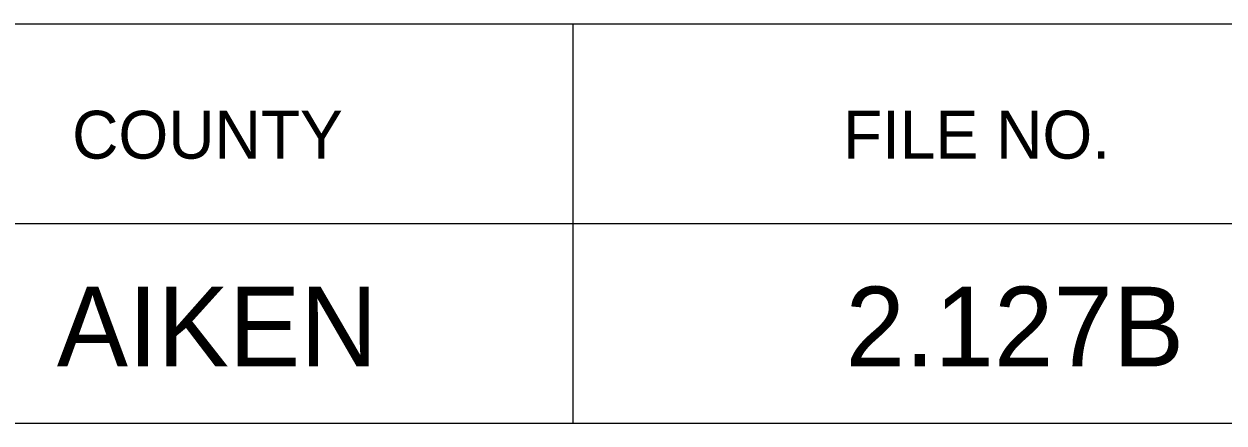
# Model space of a CAD drawing. Extents: x 1000 to 1162, y 999 to 8520.
# Drawn here: x 1140.57 to 1148.08, y 6160.05 to 6162.55 of the extents above; entities that cross this region are included whole.
import ezdxf

# ---------------------------------------------------------------- set-up
doc = ezdxf.new("R2010")
doc.units = 0
doc.layers.add('Level 20', color=7, linetype='Continuous')
doc.layers.add('Level 3', color=7, linetype='Continuous')

msp = doc.modelspace()

# ---------------------------------------------------------------- linework, layer by layer
at = {"layer": 'Level 3'}
for p, q in [((1133.055, 6162.5458), (1161.555, 6162.5458)), ((1133.055, 6162.5458), (1161.555, 6162.5458)), ((1133.055, 6162.5458), (1161.555, 6162.5458)), ((1133.055, 6162.5458), (1161.555, 6162.5458)), ((1133.055, 6162.5458), (1161.555, 6162.5458)), ((1133.055, 6162.5458), (1161.555, 6162.5458)), ((1133.055, 6162.5458), (1161.555, 6162.5458)), ((1133.055, 6162.5458), (1161.555, 6162.5458)), ((1133.055, 6162.5458), (1161.555, 6162.5458)), ((1133.055, 6162.5458), (1161.555, 6162.5458)), ((1133.055, 6162.5458), (1161.555, 6162.5458)), ((1133.055, 6162.5458), (1161.555, 6162.5458)), ((1133.055, 6162.5458), (1161.555, 6162.5458)), ((1133.055, 6162.5458), (1161.555, 6162.5458)), ((1133.055, 6162.5458), (1161.555, 6162.5458)), ((1133.055, 6162.5458), (1161.555, 6162.5458)), ((1133.055, 6162.5458), (1161.555, 6162.5458)), ((1133.055, 6162.5458), (1161.555, 6162.5458)), ((1133.055, 6162.5458), (1161.555, 6162.5458)), ((1133.055, 6162.5458), (1161.555, 6162.5458)), ((1133.055, 6162.5458), (1161.555, 6162.5458)), ((1133.055, 6162.5458), (1161.555, 6162.5458)), ((1133.055, 6162.5458), (1161.555, 6162.5458)), ((1133.055, 6162.5458), (1161.555, 6162.5458)), ((1133.055, 6162.5458), (1161.555, 6162.5458)), ((1133.055, 6162.5458), (1161.555, 6162.5458)), ((1133.055, 6162.5458), (1161.555, 6162.5458)), ((1133.055, 6162.5458), (1161.555, 6162.5458)), ((1133.055, 6162.5458), (1161.555, 6162.5458)), ((1133.055, 6162.5458), (1161.555, 6162.5458)), ((1133.055, 6162.5458), (1161.555, 6162.5458)), ((1133.055, 6162.5458), (1161.555, 6162.5458)), ((1133.055, 6162.5458), (1161.555, 6162.5458)), ((1133.055, 6162.5458), (1161.555, 6162.5458)), ((1133.055, 6162.5458), (1161.555, 6162.5458)), ((1133.055, 6162.5458), (1161.555, 6162.5458)), ((1133.055, 6162.5458), (1161.555, 6162.5458)), ((1133.055, 6162.5458), (1161.555, 6162.5458)), ((1133.055, 6162.5458), (1161.555, 6162.5458)), ((1133.055, 6162.5458), (1161.555, 6162.5458)), ((1133.055, 6162.5458), (1161.555, 6162.5458)), ((1133.055, 6162.5458), (1161.555, 6162.5458)), ((1133.055, 6162.5458), (1161.555, 6162.5458)), ((1143.9997, 6162.5458), (1143.9997, 6160.0458)), ((1143.9997, 6162.5458), (1143.9997, 6160.0458)), ((1143.9997, 6162.5458), (1143.9997, 6160.0458)), ((1143.9997, 6162.5458), (1143.9997, 6160.0458)), ((1143.9997, 6162.5458), (1143.9997, 6160.0458)), ((1143.9997, 6162.5458), (1143.9997, 6160.0458)), ((1143.9997, 6162.5458), (1143.9997, 6160.0458)), ((1143.9997, 6162.5458), (1143.9997, 6160.0458)), ((1143.9997, 6162.5458), (1143.9997, 6160.0458)), ((1143.9997, 6162.5458), (1143.9997, 6160.0458)), ((1143.9997, 6162.5458), (1143.9997, 6160.0458)), ((1143.9997, 6162.5458), (1143.9997, 6160.0458)), ((1143.9997, 6162.5458), (1143.9997, 6160.0458)), ((1143.9997, 6162.5458), (1143.9997, 6160.0458)), ((1143.9997, 6162.5458), (1143.9997, 6160.0458)), ((1143.9997, 6162.5458), (1143.9997, 6160.0458)), ((1143.9997, 6162.5458), (1143.9997, 6160.0458)), ((1143.9997, 6162.5458), (1143.9997, 6160.0458)), ((1143.9997, 6162.5458), (1143.9997, 6160.0458)), ((1143.9997, 6162.5458), (1143.9997, 6160.0458)), ((1143.9997, 6162.5458), (1143.9997, 6160.0458)), ((1143.9997, 6162.5458), (1143.9997, 6160.0458)), ((1143.9997, 6162.5458), (1143.9997, 6160.0458)), ((1143.9997, 6162.5458), (1143.9997, 6160.0458)), ((1143.9997, 6162.5458), (1143.9997, 6160.0458)), ((1143.9997, 6162.5458), (1143.9997, 6160.0458)), ((1143.9997, 6162.5458), (1143.9997, 6160.0458)), ((1143.9997, 6162.5458), (1143.9997, 6160.0458)), ((1143.9997, 6162.5458), (1143.9997, 6160.0458)), ((1143.9997, 6162.5458), (1143.9997, 6160.0458)), ((1143.9997, 6162.5458), (1143.9997, 6160.0458)), ((1143.9997, 6162.5458), (1143.9997, 6160.0458)), ((1143.9997, 6162.5458), (1143.9997, 6160.0458)), ((1143.9997, 6162.5458), (1143.9997, 6160.0458)), ((1143.9997, 6162.5458), (1143.9997, 6160.0458)), ((1143.9997, 6162.5458), (1143.9997, 6160.0458)), ((1143.9997, 6162.5458), (1143.9997, 6160.0458)), ((1143.9997, 6162.5458), (1143.9997, 6160.0458)), ((1143.9997, 6162.5458), (1143.9997, 6160.0458)), ((1143.9997, 6162.5458), (1143.9997, 6160.0458)), ((1143.9997, 6162.5458), (1143.9997, 6160.0458)), ((1143.9997, 6162.5458), (1143.9997, 6160.0458)), ((1143.9997, 6162.5458), (1143.9997, 6160.0458)), ((1133.055, 6161.2958), (1161.555, 6161.2958)), ((1133.055, 6161.2958), (1161.555, 6161.2958)), ((1133.055, 6161.2958), (1161.555, 6161.2958)), ((1133.055, 6161.2958), (1161.555, 6161.2958)), ((1133.055, 6161.2958), (1161.555, 6161.2958)), ((1133.055, 6161.2958), (1161.555, 6161.2958)), ((1133.055, 6161.2958), (1161.555, 6161.2958)), ((1133.055, 6161.2958), (1161.555, 6161.2958)), ((1133.055, 6161.2958), (1161.555, 6161.2958)), ((1133.055, 6161.2958), (1161.555, 6161.2958)), ((1133.055, 6161.2958), (1161.555, 6161.2958)), ((1133.055, 6161.2958), (1161.555, 6161.2958)), ((1133.055, 6161.2958), (1161.555, 6161.2958)), ((1133.055, 6161.2958), (1161.555, 6161.2958)), ((1133.055, 6161.2958), (1161.555, 6161.2958)), ((1133.055, 6161.2958), (1161.555, 6161.2958)), ((1133.055, 6161.2958), (1161.555, 6161.2958)), ((1133.055, 6161.2958), (1161.555, 6161.2958)), ((1133.055, 6161.2958), (1161.555, 6161.2958)), ((1133.055, 6161.2958), (1161.555, 6161.2958)), ((1133.055, 6161.2958), (1161.555, 6161.2958)), ((1133.055, 6161.2958), (1161.555, 6161.2958)), ((1133.055, 6161.2958), (1161.555, 6161.2958)), ((1133.055, 6161.2958), (1161.555, 6161.2958)), ((1133.055, 6161.2958), (1161.555, 6161.2958)), ((1133.055, 6161.2958), (1161.555, 6161.2958)), ((1133.055, 6161.2958), (1161.555, 6161.2958)), ((1133.055, 6161.2958), (1161.555, 6161.2958)), ((1133.055, 6161.2958), (1161.555, 6161.2958)), ((1133.055, 6161.2958), (1161.555, 6161.2958)), ((1133.055, 6161.2958), (1161.555, 6161.2958)), ((1133.055, 6161.2958), (1161.555, 6161.2958)), ((1133.055, 6161.2958), (1161.555, 6161.2958)), ((1133.055, 6161.2958), (1161.555, 6161.2958)), ((1133.055, 6161.2958), (1161.555, 6161.2958)), ((1133.055, 6161.2958), (1161.555, 6161.2958)), ((1133.055, 6161.2958), (1161.555, 6161.2958)), ((1133.055, 6161.2958), (1161.555, 6161.2958)), ((1133.055, 6161.2958), (1161.555, 6161.2958)), ((1133.055, 6161.2958), (1161.555, 6161.2958)), ((1133.055, 6161.2958), (1161.555, 6161.2958)), ((1133.055, 6161.2958), (1161.555, 6161.2958)), ((1133.055, 6161.2958), (1161.555, 6161.2958)), ((1133.055, 6160.0458), (1161.555, 6160.0458)), ((1133.055, 6160.0458), (1161.555, 6160.0458)), ((1133.055, 6160.0458), (1161.555, 6160.0458)), ((1133.055, 6160.0458), (1161.555, 6160.0458)), ((1133.055, 6160.0458), (1161.555, 6160.0458)), ((1133.055, 6160.0458), (1161.555, 6160.0458)), ((1133.055, 6160.0458), (1161.555, 6160.0458)), ((1133.055, 6160.0458), (1161.555, 6160.0458)), ((1133.055, 6160.0458), (1161.555, 6160.0458)), ((1133.055, 6160.0458), (1161.555, 6160.0458)), ((1133.055, 6160.0458), (1161.555, 6160.0458)), ((1133.055, 6160.0458), (1161.555, 6160.0458)), ((1133.055, 6160.0458), (1161.555, 6160.0458)), ((1133.055, 6160.0458), (1161.555, 6160.0458)), ((1133.055, 6160.0458), (1161.555, 6160.0458)), ((1133.055, 6160.0458), (1161.555, 6160.0458)), ((1133.055, 6160.0458), (1161.555, 6160.0458)), ((1133.055, 6160.0458), (1161.555, 6160.0458)), ((1133.055, 6160.0458), (1161.555, 6160.0458)), ((1133.055, 6160.0458), (1161.555, 6160.0458)), ((1133.055, 6160.0458), (1161.555, 6160.0458)), ((1133.055, 6160.0458), (1161.555, 6160.0458)), ((1133.055, 6160.0458), (1161.555, 6160.0458)), ((1133.055, 6160.0458), (1161.555, 6160.0458)), ((1133.055, 6160.0458), (1161.555, 6160.0458)), ((1133.055, 6160.0458), (1161.555, 6160.0458)), ((1133.055, 6160.0458), (1161.555, 6160.0458)), ((1133.055, 6160.0458), (1161.555, 6160.0458)), ((1133.055, 6160.0458), (1161.555, 6160.0458)), ((1133.055, 6160.0458), (1161.555, 6160.0458)), ((1133.055, 6160.0458), (1161.555, 6160.0458)), ((1133.055, 6160.0458), (1161.555, 6160.0458)), ((1133.055, 6160.0458), (1161.555, 6160.0458)), ((1133.055, 6160.0458), (1161.555, 6160.0458)), ((1133.055, 6160.0458), (1161.555, 6160.0458)), ((1133.055, 6160.0458), (1161.555, 6160.0458)), ((1133.055, 6160.0458), (1161.555, 6160.0458)), ((1133.055, 6160.0458), (1161.555, 6160.0458)), ((1133.055, 6160.0458), (1161.555, 6160.0458)), ((1133.055, 6160.0458), (1161.555, 6160.0458)), ((1133.055, 6160.0458), (1161.555, 6160.0458)), ((1133.055, 6160.0458), (1161.555, 6160.0458)), ((1133.055, 6160.0458), (1161.555, 6160.0458))]:
    msp.add_line(p, q, dxfattribs=at)

# ---------------------------------------------------------------- texts
at = {"layer": 'Level 20'}
for s, p in [('AIKEN', (1140.7706, 6160.4)), ('2.127B', (1145.7068, 6160.4))]:
    msp.add_text(s, height=0.5, dxfattribs=at).set_placement(p)
at = {"layer": 'Level 3'}
for s, p in [('COUNTY', (1140.8665, 6161.7021)), ('COUNTY', (1140.8665, 6161.7021)), ('COUNTY', (1140.8665, 6161.7021)), ('COUNTY', (1140.8665, 6161.7021)), ('COUNTY', (1140.8665, 6161.7021)), ('COUNTY', (1140.8665, 6161.7021)), ('COUNTY', (1140.8665, 6161.7021)), ('COUNTY', (1140.8665, 6161.7021)), ('COUNTY', (1140.8665, 6161.7021)), ('COUNTY', (1140.8665, 6161.7021)), ('COUNTY', (1140.8665, 6161.7021)), ('COUNTY', (1140.8665, 6161.7021)), ('COUNTY', (1140.8665, 6161.7021)), ('COUNTY', (1140.8665, 6161.7021)), ('COUNTY', (1140.8665, 6161.7021)), ('COUNTY', (1140.8665, 6161.7021)), ('COUNTY', (1140.8665, 6161.7021)), ('COUNTY', (1140.8665, 6161.7021)), ('COUNTY', (1140.8665, 6161.7021)), ('COUNTY', (1140.8665, 6161.7021)), ('COUNTY', (1140.8665, 6161.7021)), ('COUNTY', (1140.8665, 6161.7021)), ('COUNTY', (1140.8665, 6161.7021)), ('COUNTY', (1140.8665, 6161.7021)), ('COUNTY', (1140.8665, 6161.7021)), ('COUNTY', (1140.8665, 6161.7021)), ('COUNTY', (1140.8665, 6161.7021)), ('COUNTY', (1140.8665, 6161.7021)), ('COUNTY', (1140.8665, 6161.7021)), ('COUNTY', (1140.8665, 6161.7021)), ('COUNTY', (1140.8665, 6161.7021)), ('COUNTY', (1140.8665, 6161.7021)), ('COUNTY', (1140.8665, 6161.7021)), ('COUNTY', (1140.8665, 6161.7021)), ('COUNTY', (1140.8665, 6161.7021)), ('COUNTY', (1140.8665, 6161.7021)), ('COUNTY', (1140.8665, 6161.7021)), ('COUNTY', (1140.8665, 6161.7021)), ('COUNTY', (1140.8665, 6161.7021)), ('COUNTY', (1140.8665, 6161.7021)), ('COUNTY', (1140.8665, 6161.7021)), ('COUNTY', (1140.8665, 6161.7021)), ('COUNTY', (1140.8665, 6161.7021)), ('FILE NO.', (1145.6908, 6161.7021)), ('FILE NO.', (1145.6908, 6161.7021)), ('FILE NO.', (1145.6908, 6161.7021)), ('FILE NO.', (1145.6908, 6161.7021)), ('FILE NO.', (1145.6908, 6161.7021)), ('FILE NO.', (1145.6908, 6161.7021)), ('FILE NO.', (1145.6908, 6161.7021)), ('FILE NO.', (1145.6908, 6161.7021)), ('FILE NO.', (1145.6908, 6161.7021)), ('FILE NO.', (1145.6908, 6161.7021)), ('FILE NO.', (1145.6908, 6161.7021)), ('FILE NO.', (1145.6908, 6161.7021)), ('FILE NO.', (1145.6908, 6161.7021)), ('FILE NO.', (1145.6908, 6161.7021)), ('FILE NO.', (1145.6908, 6161.7021)), ('FILE NO.', (1145.6908, 6161.7021)), ('FILE NO.', (1145.6908, 6161.7021)), ('FILE NO.', (1145.6908, 6161.7021)), ('FILE NO.', (1145.6908, 6161.7021)), ('FILE NO.', (1145.6908, 6161.7021)), ('FILE NO.', (1145.6908, 6161.7021)), ('FILE NO.', (1145.6908, 6161.7021)), ('FILE NO.', (1145.6908, 6161.7021)), ('FILE NO.', (1145.6908, 6161.7021)), ('FILE NO.', (1145.6908, 6161.7021)), ('FILE NO.', (1145.6908, 6161.7021)), ('FILE NO.', (1145.6908, 6161.7021)), ('FILE NO.', (1145.6908, 6161.7021)), ('FILE NO.', (1145.6908, 6161.7021)), ('FILE NO.', (1145.6908, 6161.7021)), ('FILE NO.', (1145.6908, 6161.7021)), ('FILE NO.', (1145.6908, 6161.7021)), ('FILE NO.', (1145.6908, 6161.7021)), ('FILE NO.', (1145.6908, 6161.7021)), ('FILE NO.', (1145.6908, 6161.7021)), ('FILE NO.', (1145.6908, 6161.7021)), ('FILE NO.', (1145.6908, 6161.7021)), ('FILE NO.', (1145.6908, 6161.7021)), ('FILE NO.', (1145.6908, 6161.7021)), ('FILE NO.', (1145.6908, 6161.7021)), ('FILE NO.', (1145.6908, 6161.7021)), ('FILE NO.', (1145.6908, 6161.7021)), ('FILE NO.', (1145.6908, 6161.7021))]:
    msp.add_text(s, height=0.3, dxfattribs=at).set_placement(p)

doc.saveas('drawing.dxf')
